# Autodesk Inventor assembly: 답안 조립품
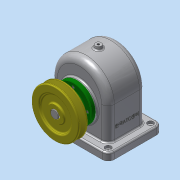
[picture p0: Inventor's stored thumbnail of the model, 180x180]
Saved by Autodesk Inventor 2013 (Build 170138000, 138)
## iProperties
Created: 2016-10
Part Number: 답안 조립품
Document SubType Name: Assembly
Designer: Administrator
Author: Administrator
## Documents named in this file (15)
- C:\Users\Administrator\Desktop\461008v1021\답안 조립품.iam
- C:\Users\Administrator\Desktop\461008v1021\본체.ipt
- C:\Users\Administrator\Desktop\461008v1021\뒤커버.ipt
- C:\Users\Administrator\Desktop\461008v1021\베어링 6203.ipt
- C:\Users\Administrator\Desktop\461008v1021\축.ipt
- C:\Users\Administrator\Desktop\461008v1021\볼트 M3 x 8.ipt
- C:\Users\Administrator\Desktop\461008v1021\스퍼기어.ipt
- C:\Users\Administrator\Desktop\461008v1021\키 - 6 x 6 x 22.ipt
- C:\Users\Administrator\Desktop\461008v1021\부시.ipt
- C:\Users\Administrator\Desktop\461008v1021\V-벨트풀리.ipt
- C:\Users\Administrator\Desktop\461008v1021\키 - 5 x 5 x 18.ipt
- C:\Users\Administrator\Desktop\461008v1021\멈춤나사 - M4x10.ipt
- C:\Users\Administrator\Desktop\461008v1021\앞커버.ipt
- C:\Users\Administrator\Desktop\461008v1021\오일씰 28 40 8.ipt
- C:\Users\Administrator\Desktop\461008v1021\볼트 M3 x 10.ipt
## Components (9 placed, 3 different names)
1. V-벨트풀리:1
2. ISO 4762 M3 x 8:1
3. ISO 4762 M3 x 8:2
4. ISO 4762 M3 x 8:3
5. ISO 4762 M3 x 8:4
6. ISO 4762 M3 x 10:1
7. ISO 4762 M3 x 10:2
8. ISO 4762 M3 x 10:3
9. ISO 4762 M3 x 10:4
